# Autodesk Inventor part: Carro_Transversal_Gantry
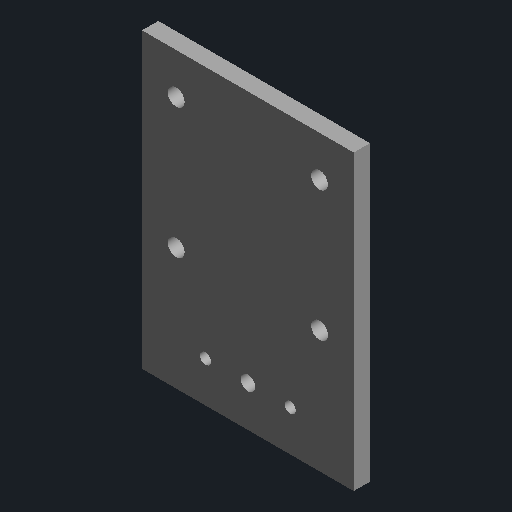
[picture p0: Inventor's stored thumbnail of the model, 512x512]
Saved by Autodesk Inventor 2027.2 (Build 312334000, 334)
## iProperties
Part Number: Carro_Transversal_Gantry
Material: Genérico
Document SubType Name: Modelado
Designer: Usuario
Appearance: Por defecto
Author: Usuario
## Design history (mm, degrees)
sketch "Boceto1"
  geometry: L1 (-32.5, -32.5)-(32.5, -32.5); L2 (32.5, -32.5)-(32.5, 32.5); L3 (32.5, 32.5)-(-32.5, 32.5); L4 (-32.5, 32.5)-(-32.5, -32.5); L5 (-32.5, -57.5)-(32.5, -57.5); L6 (32.5, -57.5)-(32.5, -32.5); L7 (32.5, -32.5)-(-32.5, -32.5); L8 (-32.5, -32.5)-(-32.5, -57.5); C1 r 2.6 at (-22, 20); C2 r 2.6 at (22, 20); C3 r 2.6 at (-22, -20); C4 r 2.6 at (22, -20); C5 r 2.25 at (0, -45); C6 r 1.7 at (-13, -45); C7 r 1.7 at (13, -45)
  constraints: 16 end point, 7 centre point, 4 parallel, 2 horizontal, 2 perpendicular
extrude "Extrusión1" new body sketch "Boceto1" distance "d0" = 5; taper "d1" = 0 deg
node "Sólido1"
node "Cuerpos sólidos"
node "Cuerpos de superficie"
